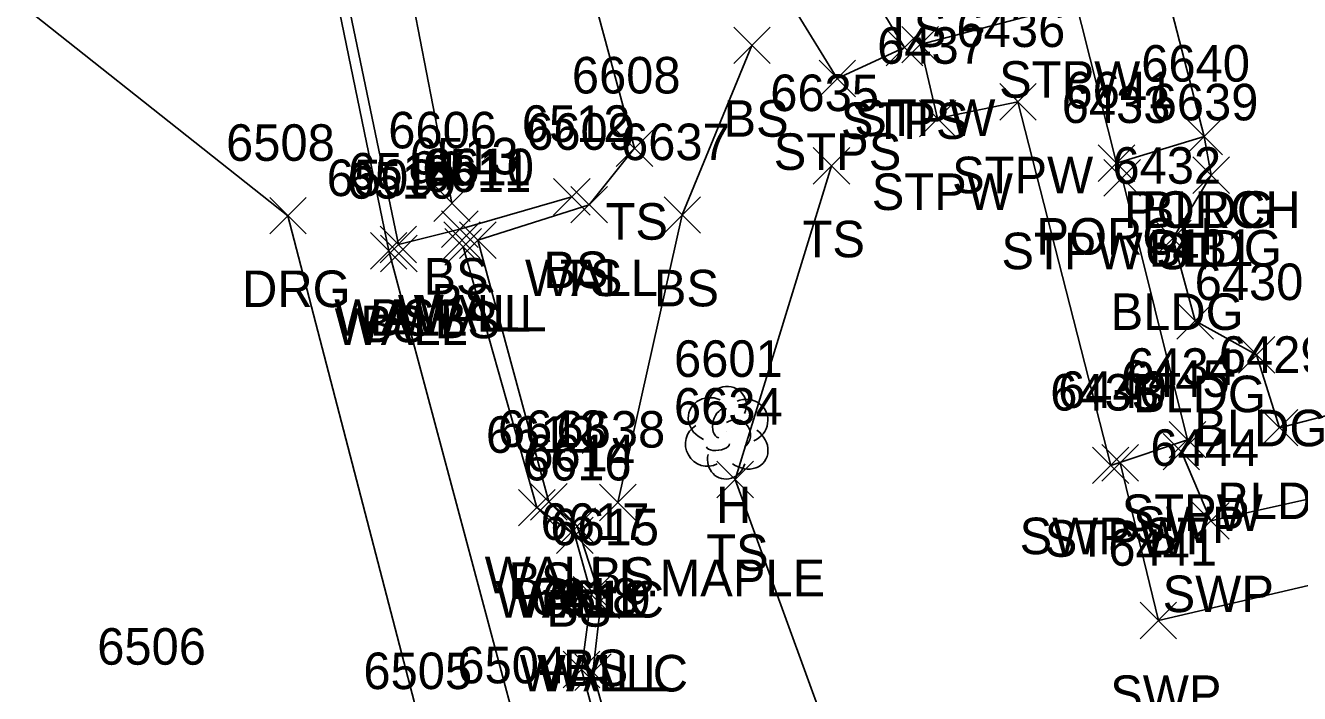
# Model space of a CAD drawing. Extents: x 1769141 to 1770817, y 735471 to 742405.
# Drawn here: x 1770229.2 to 1770299, y 740786.6 to 740823.1 of the extents above; entities that cross this region are included whole.
import ezdxf

# ---------------------------------------------------------------- set-up
doc = ezdxf.new("R2010")
doc.units = 0
for name, color, linetype in [('L_A', 7, 'Continuous'), ('L_C', 7, 'Continuous'), ('L_I', 7, 'Continuous'), ('L_TIC', 7, 'Continuous'), ('LBC', 7, 'Continuous'), ('LBF', 7, 'Continuous'), ('LELB', 7, 'Continuous'), ('LTD', 7, 'Continuous'), ('LW', 7, 'Continuous'), ('R_A', 7, 'Continuous'), ('R_I', 7, 'Continuous'), ('R_TIC', 7, 'Continuous'), ('RDG', 7, 'Continuous'), ('RSW', 7, 'Continuous')]:
    doc.layers.add(name, color=color, linetype=linetype)

msp = doc.modelspace()

# ---------------------------------------------------------------- linework, layer by layer
at = {"layer": 'L_TIC'}
for points in [[(1770268.008, 740821.019), (1770270.008, 740823.019)], [(1770270.008, 740821.019), (1770268.008, 740823.019)], [(1770277.212, 740821.059), (1770279.212, 740823.059)], [(1770279.212, 740821.059), (1770277.212, 740823.059)], [(1770276.355, 740820.898), (1770278.355, 740822.898)], [(1770278.355, 740820.898), (1770276.355, 740822.898)], [(1770272.678, 740819.206), (1770274.678, 740821.206)], [(1770274.678, 740819.206), (1770272.678, 740821.206)], [(1770282.566, 740817.929), (1770284.566, 740819.929)], [(1770284.566, 740817.929), (1770282.566, 740819.929)], [(1770278.169, 740817.012), (1770280.169, 740819.012)], [(1770280.169, 740817.012), (1770278.169, 740819.012)], [(1770292.756, 740816.035), (1770294.756, 740818.035)], [(1770294.756, 740816.035), (1770292.756, 740818.035)], [(1770292.756, 740816.035), (1770294.756, 740818.035)], [(1770294.756, 740816.035), (1770292.756, 740818.035)], [(1770261.583, 740815.387), (1770263.583, 740817.387)], [(1770263.583, 740815.387), (1770261.583, 740817.387)], [(1770272.364, 740814.423), (1770274.364, 740816.423)], [(1770274.364, 740814.423), (1770272.364, 740816.423)], [(1770287.955, 740814.572), (1770289.955, 740816.572)], [(1770289.955, 740814.572), (1770287.955, 740816.572)], [(1770288.268, 740813.772), (1770290.268, 740815.772)], [(1770290.268, 740813.772), (1770288.268, 740815.772)], [(1770293.139, 740813.916), (1770295.139, 740815.916)], [(1770295.139, 740813.916), (1770293.139, 740815.916)], [(1770258.147, 740812.738), (1770260.147, 740814.738)], [(1770260.147, 740812.738), (1770258.147, 740814.738)], [(1770251.587, 740812.383), (1770253.587, 740814.383)], [(1770253.587, 740812.383), (1770251.587, 740814.383)], [(1770259.091, 740812.303), (1770261.091, 740814.303)], [(1770261.091, 740812.303), (1770259.091, 740814.303)], [(1770259.091, 740812.303), (1770261.091, 740814.303)], [(1770261.091, 740812.303), (1770259.091, 740814.303)], [(1770264.195, 740811.739), (1770266.195, 740813.739)], [(1770266.195, 740811.739), (1770264.195, 740813.739)], [(1770252.02, 740810.959), (1770254.02, 740812.959)], [(1770254.02, 740810.959), (1770252.02, 740812.959)], [(1770248.653, 740810.13), (1770250.653, 740812.13)], [(1770250.653, 740810.13), (1770248.653, 740812.13)], [(1770248.653, 740810.13), (1770250.653, 740812.13)], [(1770250.653, 740810.13), (1770248.653, 740812.13)], [(1770252.136, 740810.358), (1770254.136, 740812.358)], [(1770254.136, 740810.358), (1770252.136, 740812.358)], [(1770252.204, 740809.995), (1770254.204, 740811.995)], [(1770254.204, 740809.995), (1770252.204, 740811.995)], [(1770252.998, 740810.367), (1770254.998, 740812.367)], [(1770254.998, 740810.367), (1770252.998, 740812.367)], [(1770291.047, 740810.448), (1770293.047, 740812.448)], [(1770293.047, 740810.448), (1770291.047, 740812.448)], [(1770248.122, 740809.772), (1770250.122, 740811.772)], [(1770250.122, 740809.772), (1770248.122, 740811.772)], [(1770248.676, 740809.632), (1770250.676, 740811.632)], [(1770250.676, 740809.632), (1770248.676, 740811.632)], [(1770292.266, 740805.948), (1770294.266, 740807.948)], [(1770294.266, 740805.948), (1770292.266, 740807.948)], [(1770295.632, 740804.083), (1770297.632, 740806.083)], [(1770297.632, 740804.083), (1770295.632, 740806.083)], [(1770296.879, 740800.102), (1770298.879, 740802.102)], [(1770298.879, 740800.102), (1770296.879, 740802.102)], [(1770291.85, 740799.446), (1770293.85, 740801.446)], [(1770293.85, 740799.446), (1770291.85, 740801.446)], [(1770287.641, 740798.039), (1770289.641, 740800.039)], [(1770289.641, 740798.039), (1770287.641, 740800.039)], [(1770267.092, 740797.27), (1770269.092, 740799.27)], [(1770269.092, 740797.27), (1770267.092, 740799.27)], [(1770256.889, 740796.044), (1770258.889, 740798.044)], [(1770258.889, 740796.044), (1770256.889, 740798.044)], [(1770260.662, 740796.012), (1770262.662, 740798.012)], [(1770262.662, 740796.012), (1770260.662, 740798.012)], [(1770256.233, 740795.726), (1770258.233, 740797.726)], [(1770258.233, 740795.726), (1770256.233, 740797.726)], [(1770258.445, 740794.713), (1770260.445, 740796.713)], [(1770260.445, 740794.713), (1770258.445, 740796.713)], [(1770258.445, 740794.713), (1770260.445, 740796.713)], [(1770260.445, 740794.713), (1770258.445, 740796.713)], [(1770258.308, 740794.214), (1770260.308, 740796.214)], [(1770260.308, 740794.214), (1770258.308, 740796.214)], [(1770259.228, 740790.961), (1770261.228, 740792.961)], [(1770261.228, 740790.961), (1770259.228, 740792.961)], [(1770259.758, 740790.668), (1770261.758, 740792.668)], [(1770261.758, 740790.668), (1770259.758, 740792.668)], [(1770259.758, 740790.668), (1770261.758, 740792.668)], [(1770261.758, 740790.668), (1770259.758, 740792.668)], [(1770258.678, 740786.869), (1770260.678, 740788.869)], [(1770260.678, 740786.869), (1770258.678, 740788.869)], [(1770259.305, 740786.729), (1770261.305, 740788.729)], [(1770261.305, 740786.729), (1770259.305, 740788.729)]]:
    msp.add_lwpolyline(points, dxfattribs=at)
at = {"layer": 'LBC'}
msp.add_lwpolyline([(1770319.128, 740806.628), (1770297.879, 740801.102), (1770296.632, 740805.083), (1770293.266, 740806.948), (1770292.047, 740811.448), (1770294.139, 740814.916), (1770293.756, 740817.035), (1770290.358, 740830.172), (1770289.843, 740831.832), (1770286.419, 740833.621), (1770285.236, 740838.24), (1770287.378, 740841.622), (1770286.406, 740845.581), (1770294.231, 740847.568)], dxfattribs=at)
at = {"layer": 'LBF'}
for points in [[(1770245.325, 740841.415), (1770247.569, 740845.563), (1770253.438, 740850.19), (1770258.102, 740843.366), (1770266.39, 740832.043), (1770273.678, 740820.206), (1770277.355, 740821.898), (1770269.905, 740834.153), (1770261.108, 740845.521), (1770254.984, 740855.047), (1770247.946, 740851.065), (1770240.775, 740844.318)], [(1770293.756, 740817.035), (1770288.955, 740815.572), (1770285.596, 740828.891), (1770290.358, 740830.172)], [(1770289.268, 740814.772), (1770292.85, 740800.446), (1770288.641, 740799.039), (1770283.566, 740818.929), (1770279.169, 740818.012), (1770278.212, 740822.059), (1770286.142, 740824.155)]]:
    msp.add_lwpolyline(points, dxfattribs=at)
at = {"layer": 'LELB'}
for points in [[(1770255.198, 740843.585), (1770262.583, 740816.387), (1770260.091, 740813.303)], [(1770333.692, 740767.829), (1770307.925, 740759.691), (1770284.172, 740751.04), (1770275.373, 740749.173), (1770270.306, 740749.99), (1770266.387, 740754.529), (1770256.269, 740784.114), (1770249.122, 740810.772), (1770244.481, 740833.358), (1770244.781, 740838.92), (1770245.325, 740841.415)], [(1770248.583, 740840.061), (1770249.111, 740831.282), (1770252.587, 740813.383)], [(1770269.008, 740822.019), (1770265.195, 740812.739), (1770261.662, 740797.012)], [(1770326.749, 740777.797), (1770299.87, 740770.01), (1770277.671, 740765.195), (1770276.748, 740774.479), (1770268.092, 740798.27), (1770273.364, 740815.423)], [(1770259.147, 740813.738), (1770253.02, 740811.959), (1770249.653, 740811.13)], [(1770253.204, 740810.995), (1770257.233, 740796.726), (1770259.308, 740795.214), (1770260.228, 740791.961), (1770259.678, 740787.869), (1770263.42, 740774.076), (1770269.165, 740757.316), (1770271.366, 740754.234), (1770275.46, 740752.556), (1770291.434, 740756.453)]]:
    msp.add_lwpolyline(points, dxfattribs=at)
at = {"layer": 'LTD'}
msp.add_line((1770267.607, 740800.88), (1770267.607, 740800.88), dxfattribs=at)
msp.add_line((1770267.607, 740800.88), (1770267.607, 740800.88), dxfattribs=at)
msp.add_arc((1770267.654, 740802.314), 1.047, 335.52715, 180.95627, dxfattribs=at)
for centre, major_axis, ratio, start_param, end_param in [((1770266.815, 740801.547), (1.21, -0.512), 0.895232, 1.570796, 4.712389), ((1770268.649, 740801.464), (-1.141, -0.483), 0.949671, 1.570796, 4.712389), ((1770267.399, 740801.339), (-0.208, -0.792), 0.645439, 3.141593, 6.283185), ((1770268.107, 740800.714), (-0.5, 0.667), 0.989748, 3.141593, 6.283185), ((1770266.524, 740800.172), (0.584, -1.042), 0.959034, 3.141593, 6.283185), ((1770268.607, 740800.047), (-1.09, 0.792), 0.841452, 1.570796, 4.712389), ((1770267.149, 740800.13), (-0.625, -0.083), 0.423636, 0, 3.141593), ((1770267.608, 740799.38), (0.265, 1.061), 0.942809, 1.570796, 4.712389)]:
    msp.add_ellipse(centre, major_axis=major_axis, ratio=ratio, start_param=start_param, end_param=end_param, dxfattribs=at)
at = {"layer": 'LW'}
for points in [[(1770249.653, 740811.13), (1770245.032, 740833.383), (1770245.547, 740839.06), (1770245.926, 740841.408), (1770247.72, 740845.239), (1770253.279, 740849.615), (1770257.51, 740843.175)], [(1770260.091, 740813.303), (1770253.998, 740811.367), (1770257.889, 740797.044), (1770259.445, 740795.713)], [(1770259.445, 740795.713), (1770260.758, 740791.668)], [(1770260.758, 740791.668), (1770260.305, 740787.729), (1770264.049, 740774.16), (1770269.913, 740757.542), (1770271.858, 740754.828), (1770275.345, 740753.426), (1770291.127, 740757.407)]]:
    msp.add_lwpolyline(points, dxfattribs=at)
at = {"layer": 'R_TIC'}
for points in [[(1770242.609, 740811.701), (1770244.609, 740813.701)], [(1770244.609, 740811.701), (1770242.609, 740813.701)], [(1770291.512, 740798.787), (1770293.512, 740800.787)], [(1770293.512, 740798.787), (1770291.512, 740800.787)], [(1770288.158, 740798.18), (1770290.158, 740800.18)], [(1770290.158, 740798.18), (1770288.158, 740800.18)], [(1770293.122, 740795.011), (1770295.122, 740797.011)], [(1770295.122, 740795.011), (1770293.122, 740797.011)], [(1770290.252, 740789.547), (1770292.252, 740791.547)], [(1770292.252, 740789.547), (1770290.252, 740791.547)]]:
    msp.add_lwpolyline(points, dxfattribs=at)
at = {"layer": 'RDG'}
for points in [[(1770225.064, 740827.369), (1770243.609, 740812.701)], [(1770334.527, 740765.967), (1770308.335, 740757.217), (1770284.491, 740749.702), (1770275.242, 740747.93), (1770267.767, 740748.16), (1770256.736, 740754.841), (1770254.693, 740761.852), (1770251.123, 740783.798), (1770243.609, 740812.701)]]:
    msp.add_lwpolyline(points, dxfattribs=at)
at = {"layer": 'RSW'}
for points in [[(1770321.183, 740802.043), (1770294.122, 740796.011), (1770292.512, 740799.787)], [(1770289.158, 740799.18), (1770291.252, 740790.547), (1770321.91, 740797.7)]]:
    msp.add_lwpolyline(points, dxfattribs=at)

# ---------------------------------------------------------------- texts
at = {"layer": 'L_A'}
for s, p in [('TS', (1770276.225, 740821.928)), ('STPW', (1770282.536, 740819.155)), ('BS', (1770267.449, 740817.019)), ('STPS', (1770273.875, 740816.898)), ('STPW', (1770274.606, 740817.059)), ('STPS', (1770270.197, 740815.206)), ('STPW', (1770279.96, 740813.929)), ('STPW', (1770275.563, 740813.012)), ('PORCH', (1770289.378, 740812.035)), ('BLDG', (1770290.346, 740812.035)), ('TS', (1770260.993, 740811.387)), ('PORCH', (1770284.577, 740810.572)), ('TS', (1770271.773, 740810.423)), ('BLDG', (1770290.729, 740809.916)), ('STPW ST', (1770282.661, 740809.772)), ('BS', (1770257.588, 740808.738)), ('BS', (1770251.028, 740808.383)), ('WALL', (1770256.579, 740808.303)), ('TS', (1770258.5, 740808.303)), ('BS', (1770263.636, 740807.739)), ('WALL', (1770249.624, 740806.358)), ('WALL', (1770250.487, 740806.367)), ('BS', (1770251.461, 740806.959)), ('BLDG', (1770288.637, 740806.448)), ('WALL', (1770246.141, 740806.13)), ('BS', (1770247.563, 740805.772)), ('BS', (1770248.094, 740806.13)), ('BS', (1770251.645, 740805.995)), ('WALL', (1770246.164, 740805.632)), ('BLDG', (1770289.856, 740801.948)), ('BLDG', (1770293.222, 740800.083)), ('BLDG', (1770294.47, 740796.102)), ('H', (1770267.04, 740795.88)), ('STPW', (1770289.244, 740795.446)), ('STPW', (1770285.034, 740794.039)), ('TS', (1770266.501, 740793.27)), ('WALL', (1770254.377, 740792.044)), ('BS', (1770255.674, 740791.726)), ('BS', (1770260.103, 740792.012)), ('WALLC', (1770254.98, 740790.713)), ('WALL', (1770255.933, 740790.713)), ('BS', (1770257.749, 740790.214)), ('BS', (1770258.669, 740786.961)), ('WALLC', (1770256.294, 740786.668)), ('WALL', (1770257.246, 740786.668))]:
    msp.add_text(s, height=2, dxfattribs=at).set_placement(p)
at = {"layer": 'L_C'}
msp.add_text('L.MAPLE', height=2, dxfattribs=at).set_placement((1770261.718, 740791.88))
at = {"layer": 'L_I'}
for s, p in [('6436', (1770280.204, 740821.929)), ('6437', (1770275.862, 740821.012)), ('6640', (1770290.315, 740820.035)), ('6640', (1770290.315, 740820.035)), ('6608', (1770259.15, 740819.387)), ('6635', (1770270.009, 740818.423)), ('6641', (1770286.167, 740818.572)), ('6433', (1770285.961, 740817.772)), ('6639', (1770290.777, 740817.916)), ('6606', (1770249.099, 740816.383)), ('6512', (1770256.407, 740816.738)), ('6609', (1770256.65, 740816.303)), ('6609', (1770256.65, 740816.303)), ('6637', (1770261.841, 740815.739)), ('6513', (1770250.28, 740814.959)), ('6514', (1770246.913, 740814.13)), ('6514', (1770246.913, 740814.13)), ('6511', (1770250.963, 740814.358)), ('6610', (1770251.124, 740814.367)), ('6432', (1770288.74, 740814.448)), ('6509', (1770245.729, 740813.772)), ('6510', (1770246.849, 740813.632)), ('6611', (1770250.984, 740813.995)), ('6431', (1770290.526, 740809.948)), ('6430', (1770293.238, 740808.083)), ('6601', (1770264.741, 740803.88)), ('6429', (1770294.564, 740804.102)), ('6434', (1770289.543, 740803.446)), ('6435', (1770285.334, 740802.039)), ('6634', (1770264.737, 740801.27)), ('6612', (1770254.446, 740799.726)), ('6613', (1770255.101, 740800.044)), ('6638', (1770258.308, 740800.012)), ('6614', (1770256.657, 740798.713)), ('6614', (1770256.657, 740798.713)), ('6616', (1770256.465, 740798.214)), ('6617', (1770257.44, 740794.961)), ('6615', (1770257.971, 740794.668)), ('6615', (1770257.971, 740794.668)), ('6618', (1770256.891, 740790.869)), ('6619', (1770257.51, 740790.729)), ('6506', (1770233.17, 740788.134)), ('6504', (1770252.883, 740787.114))]:
    msp.add_text(s, height=2, dxfattribs=at).set_placement(p)
at = {"layer": 'R_A'}
for s, p in [('DRG', (1770241.097, 740807.701)), ('SWP', (1770289.874, 740794.787)), ('SWP ST', (1770283.654, 740794.18)), ('SWP', (1770291.484, 740791.011)), ('SWP', (1770288.614, 740785.547))]:
    msp.add_text(s, height=2, dxfattribs=at).set_placement(p)
at = {"layer": 'R_I'}
for s, p in [('6508', (1770240.223, 740815.701)), ('6440', (1770285.764, 740802.18)), ('6445', (1770289.205, 740802.787)), ('6444', (1770290.815, 740799.011)), ('6441', (1770288.512, 740793.547)), ('6505', (1770247.738, 740786.798))]:
    msp.add_text(s, height=2, dxfattribs=at).set_placement(p)

doc.saveas('drawing.dxf')
